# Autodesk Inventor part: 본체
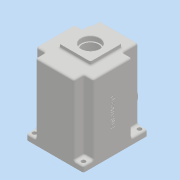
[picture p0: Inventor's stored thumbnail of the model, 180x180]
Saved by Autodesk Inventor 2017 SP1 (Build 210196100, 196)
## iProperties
Part Number: 본체
Material: 일반
Document SubType Name: Modeling
Designer: MRC
Density: 1 g/cm^3
Appearance: 기본값
Author: MRC
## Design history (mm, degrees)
sketch "스케치1"
  geometry: L1 (-49, -55)-(49, 55); L2 (49, -55)-(-49, 55); L3 (49, 55)-(33, 55); L4 (33, 55)-(33, 28); L5 (33, 28)-(49, 28); L6 (49, 28)-(49, 55); L7 (49, -55)-(33, -55); L8 (33, -55)-(33, -38); L9 (33, -38)-(49, -38); L10 (49, -38)-(49, -55); L11 (-49, -55)-(-33, -55); L12 (-33, -55)-(-33, -38); L13 (-33, -38)-(-49, -38); L14 (-49, -38)-(-49, -55); L15 (-49, 55)-(-33, 55); L16 (-33, 55)-(-33, 28); L17 (-33, 28)-(-49, 28); L18 (-49, 28)-(-49, 55); L19 (-49, 28)-(-49, -38); L20 (49, 28)-(49, -38); L21 (-33, 55)-(33, 55); L22 (-33, -55)-(33, -55); 1 further point
  constraints: 44 end point, 8 parallel, 4 horizontal, 4 perpendicular, 2 collinear, 2 midpoint, 2 vertical, 1 point on line
  dimensions: "d0" = 98 distance of L2.end L1.end; "d1" = 110 distance of L1.end L2.start; "d2" = 16 distance of L5.end L4.end; "d3" = 27 distance of L3.end L4.end; "d4" = 16 distance of L8.end L9.end; "d5" = 17 distance of L7.end L8.end; "d6" = 16 distance of L13.end L12.end; "d7" = 17 distance of L12.end L11.end; "d8" = 16 distance of L16.end L17.end; "d9" = 27 distance of L15.end L16.end; "d10" = 41.6981 deg angle of L10 L1
extrude "돌출1" new body sketch "스케치1" stored distance "d11" = 130; taper "d12" = 0 deg
sketch "스케치2"
  geometry: L1 (-33, 55)-(-33, 28) reference; L2 (-33, 28)-(-49, 28) reference; L3 (-49, 28)-(-49, -38) reference; L4 (-49, -38)-(-33, -38) reference; L5 (-33, -38)-(-33, -55) reference; L6 (-33, -55)-(33, -55) reference; L7 (33, -55)-(33, -38) reference; L8 (33, -38)-(49, -38) reference; L9 (49, -38)-(49, 28) reference; L10 (49, 28)-(33, 28) reference; L11 (33, 28)-(33, 55) reference; L12 (33, 55)-(-33, 55) reference; L13 (-49, -55)-(49, -55); L14 (49, -55)-(49, 55); L15 (49, 55)-(-49, 55); L16 (-49, 55)-(-49, -55); L17 (-49, -55)-(49, 55); L18 (49, -55)-(-49, 55); 1 further point
  constraints: 12 end point, 2 midpoint, 2 parallel, 1 horizontal, 1 perpendicular
  dimensions: "d13" = 98 distance of L14.end L15.end; "d14" = 110 distance of L13.end L14.end
extrude "돌출2" join sketch "스케치2" distance "d15" = 10; taper "d16" = 0 deg
sketch "스케치3"
  geometry: L1 (-27, 33)-(27, 33); L2 (27, 33)-(27, -21); L3 (27, -21)-(-27, -21); L4 (-27, -21)-(-27, 33); L5 (-27, 33)-(27, -21); L6 (27, 33)-(-27, -21); L7 (-33, -55)-(33, -55) reference; 3 further points
  constraints: 12 end point, 3 midpoint, 2 parallel, 1 horizontal, 1 perpendicular, 1 vertical alignment
  dimensions: "d18" = 54 distance of L1.start L1.end; "d19" = 54 distance of L1.end L2.end; "d46" = 61 distance from line of L7 point (0, 6)
extrude "돌출3" join sketch "스케치3" distance "d20" = 7; taper "d21" = 0 deg
sketch "스케치5"
  geometry: L1 (27, 33)-(-27, 33) reference; L2 (27, 33)-(-27, 33) reference; L3 (-27, 33)-(-27, -21) reference; L4 (-27, -21)-(27, -21) reference; L5 (27, -21)-(27, 33) reference; C1 r 16 at (0, 6); 1 further point
  constraints: 1 centre point, 1 vertical alignment
  dimensions: "d22" = 32 diameter of C1; "d23" = 27 distance from line of C1.centre L1
extrude "돌출4" cut sketch "스케치5" distance "d24" = 8.3; taper "d25" = 0 deg
sketch "스케치6"
  geometry: L1 (49, 55)-(-49, 55) reference; L2 (-49, -55)-(49, -55) reference; L3 (49, -55)-(49, 55) reference; L4 (-26, 48)-(26, 48); L5 (26, 48)-(26, 31.729); L6 (-26, 31.729)-(-26, 48); A1 r 45 centre (0, -5) between (-26, 31.729) and (26, 31.729); 2 further points
  constraints: 6 end point, 2 point on circle, 2 vertical alignment, 1 centre point, 1 horizontal, 1 parallel, 1 perpendicular
  dimensions: "d28" = 90 diameter of A1; "d29" = 50 distance from line of L2 A1.centre; "d30" = 53 distance from line of A1.centre L4; "d31" = 52 distance between parallel lines of L5 L6; "d32" = 23 distance between parallel lines of L3 L5; "d33" = 25.02005 distance from line of point (0, 29.98) L1
extrude "돌출5" cut sketch "스케치6" distance "d34" = 9; taper "d35" = 0 deg
sketch "스케치7"
  geometry: L1 (-26, 48)-(26, 48) reference; L2 (-26, 31.729)-(-26, 48) reference; L3 (26, 48)-(26, 31.729) reference; L4 (-23, 30.143)-(-23, 45); L5 (-23, 45)-(23, 45); L6 (23, 45)-(23, 30.143); A1 r 45 centre (0, -5) between (-26, 31.729) and (26, 31.729) reference; A2 r 42 centre (0, -5) between (-23, 30.143) and (23, 30.143); 1 further point
  constraints: 6 end point, 2 point on circle, 1 centre point, 3 other
  dimensions: "d36" = 3 radial gap between concentric circles of A1 A2
fillet "모깎기1" dims "d37" = 3
extrude "돌출6" cut sketch "스케치7" distance "d38" = 112; taper "d39" = 0 deg
sketch "스케치8"
  geometry: C1 r 21 at (0, 6); C2 r 15 at (0, -25); A1 r 42 centre (0, -5) between (-23, 30.143) and (23, 30.143) reference; 1 further point
  constraints: 2 centre point, 2 vertical alignment
  dimensions: "d40" = 42 diameter of C1; "d41" = 30 diameter of C2; "d42" = 20 distance of C2.centre A1.centre; "d43" = 11 distance of C1.centre A1.centre
extrude "돌출7" join sketch "스케치8" distance "d44" = 7; taper "d45" = 0 deg
sketch "스케치9"
  geometry: C1 r 17.5 at (0, 6); A1 r 21 centre (0, 6) between (8.978, -12.984) and (-8.978, -12.984) reference; 1 further point
  constraints: 1 centre point, 1 coincident
  dimensions: "d47" = 35 diameter of C1
extrude "돌출8" cut sketch "스케치9" distance "d48" = 10; taper "d49" = 0 deg
sketch "스케치10"
  geometry: C1 r 17.5 at (0, 0) reference; C2 r 14 at (0, 0); 1 further point
  constraints: 1 centre point, 1 coincident
  dimensions: "d50" = 28 diameter of C2
extrude "돌출9" cut sketch "스케치10" stored distance "d51" = 10; taper "d52" = 0 deg
sketch "스케치11"
  geometry: A1 r 15 centre (0, -25) between (-8.978, -12.984) and (8.978, -12.984) reference; 2 further points
  constraints: 1 coincident
hole "구멍1" sketch "스케치11" at (0, -25) diameter "d53" = 19; stored, may be unused: countersink angle "d57" = 90 deg, drill point angle "d59" = 0 deg; dims "d54" = 6, "d55" = 22, "d56" = 7, "d58" = 10
fillet "모깎기2" dims "d60" = 3
sketch "스케치12" dims "d61" = 72
  geometry: L1 (-36, -1)-(-41.809, -1); L2 (-36, -9)-(-41.809, -9); A1 r 42 centre (0, -5) between (-23, 30.143) and (23, 30.143) reference; A2 r 45 centre (0, -5) between (-26, 31.729) and (26, 31.729) reference; A3 r 4 centre (-36, -5) between (-36, -9) and (-36, -1); 2 further points
  constraints: 4 end point, 4 point on circle, 2 horizontal, 2 horizontal alignment, 2 tangent, 1 centre point, 1 coincident, 3 other
  dimensions: "d62" = 8 diameter of A3
extrude "돌출10" join sketch "스케치12" stored distance "d63" = 10; taper "d64" = 0 deg
sketch "스케치13"
  geometry: A1 r 4 centre (-36, -5) between (-36, -9) and (-36, -1) reference; 2 further points
  constraints: 1 coincident
hole "구멍2" sketch "스케치13" at (-36, -5) diameter "d65" = 3.242; stored, may be unused: countersink angle "d69" = 90 deg, drill point angle "d71" = 118 deg; dims "d66" = 7, "d67" = 22, "d68" = 7, "d70" = 9
fillet "모깎기3" dims "d72" = 3
fillet "모깎기18" dims "d130" = 6
fillet "모깎기4" dims "d73" = 3
fillet "모깎기5" dims "d74" = 3
sketch "스케치14"
  geometry: L1 (0, 0)-(98, 0) reference; C1 r 22.5 at (49, -40); C2 r 15 at (49, -89); 1 further point
  constraints: 2 centre point, 2 vertical alignment
  dimensions: "d75" = 40 distance from line of L1 C1.centre; "d76" = 49 distance of C1.centre C2.centre; "d77" = 45 diameter of C1; "d78" = 30 diameter of C2
extrude "돌출11" join sketch "스케치14" distance "d79" = 10; taper "d80" = 0 deg
extrude "돌출12" join sketch "스케치14" distance "d81" = 5; taper "d82" = 0 deg
hole "구멍3" diameter "d85" = 33.376; stored, may be unused: countersink angle "d89" = 90 deg, drill point angle "d91" = 118 deg; dims "d83" = 10, "d84" = 10, "d86" = 70, "d87" = 22, "d88" = 7, "d90" = 77.3
sketch "스케치17"
  geometry: C1 r 10 at (0, 0); 2 further points
  constraints: 1 centre point, 1 coincident, 1 vertical alignment
  dimensions: "d92" = 20 diameter of C1
extrude "돌출13" cut sketch "스케치17" stored distance "d93" = 5; taper "d94" = 0 deg
sketch "스케치18"
  geometry: C1 r 10 at (20, 80) reference; C2 r 15 at (20, 80); 1 further point
  constraints: 1 centre point, 1 coincident
  dimensions: "d95" = 30 diameter of C2
extrude "돌출14" cut sketch "스케치18" distance "d96" = 5; taper "d97" = 0 deg
sketch "스케치19"
  geometry: L1 (49, 28)-(49, 55) reference; L2 (49, 55)-(33, 55) reference; L3 (-49, 55)-(-49, 28) reference; L4 (-49, -55)-(-33, -55) reference; 5 further points
  constraints: 2 horizontal alignment, 2 vertical alignment
  dimensions: "d98" = 7 distance from line of L2 point (42, 48); "d99" = 7 distance from line of L1 point (42, 48); "d100" = 7 distance from line of L3 point (-42, 48); "d101" = 7 distance from line of L4 point (-42, -48)
hole "구멍4" sketch "스케치19" at (42, 48), (-42, 48), (-42, -48), (42, -48) diameter "d102" = 7; stored, may be unused: countersink angle "d106" = 90 deg, drill point angle "d108" = 0 deg; dims "d103" = 70, "d104" = 22, "d105" = 7, "d107" = 77.3
fillet "모깎기6" dims "d109" = 3
fillet "모깎기7" dims "d110" = 3
fillet "모깎기8" dims "d111" = 3
fillet "모깎기9" dims "d112" = 3
fillet "모깎기10" dims "d113" = 3
fillet "모깎기11" dims "d114" = 3
fillet "모깎기12" dims "d115" = 3
fillet "모깎기13" dims "d116" = 3
chamfer "모따기1" distance "d117" = 0.8; stored, may be unused: second distance "d118" = 2, angle "d119" = 30 deg
fillet "모깎기14" dims "d120" = 0.3
chamfer "모따기2" distance "d121" = 1; stored, may be unused: second distance "d122" = 2, angle "d123" = 30 deg
fillet "모깎기15" dims "d124" = 3
chamfer "모따기3" distance "d125" = 1; stored, may be unused: second distance "d126" = 2, angle "d127" = 30 deg
fillet "모깎기16" dims "d128" = 3
fillet "모깎기17" dims "d129" = 3
sketch "스케치20"
  geometry: L1 (-13, 80)-(-127, 80) reference; L2 (-130, 104)-(-130, 83) reference; 2 further points
  constraints: 1 other
  dimensions: "d131" = 33 distance from line of point (-65, 47) L1; "d132" = 65 distance from line of point (-65, 47) L2
feature "엠보싱1" sketch "스케치20" dims "d133" = 0.5, "d134" = 0
node "솔리드1"
mirror "미러1"
node "투영된 루프1"
